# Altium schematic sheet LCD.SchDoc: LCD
size A4; Date: Not used; ApprovedBy: Not used; CheckedBy: Not used; Author: Not used; CompanyName: STMicroelectronics; DrawnBy: Not used; Engineer: Not used; Organization: Not used; Address1: Not used; Address2: Not used; Address3: Not used; Address4: Not used; DocumentNumber: Not used; Revision: Not used; SheetNumber: 13; SheetTotal: 23
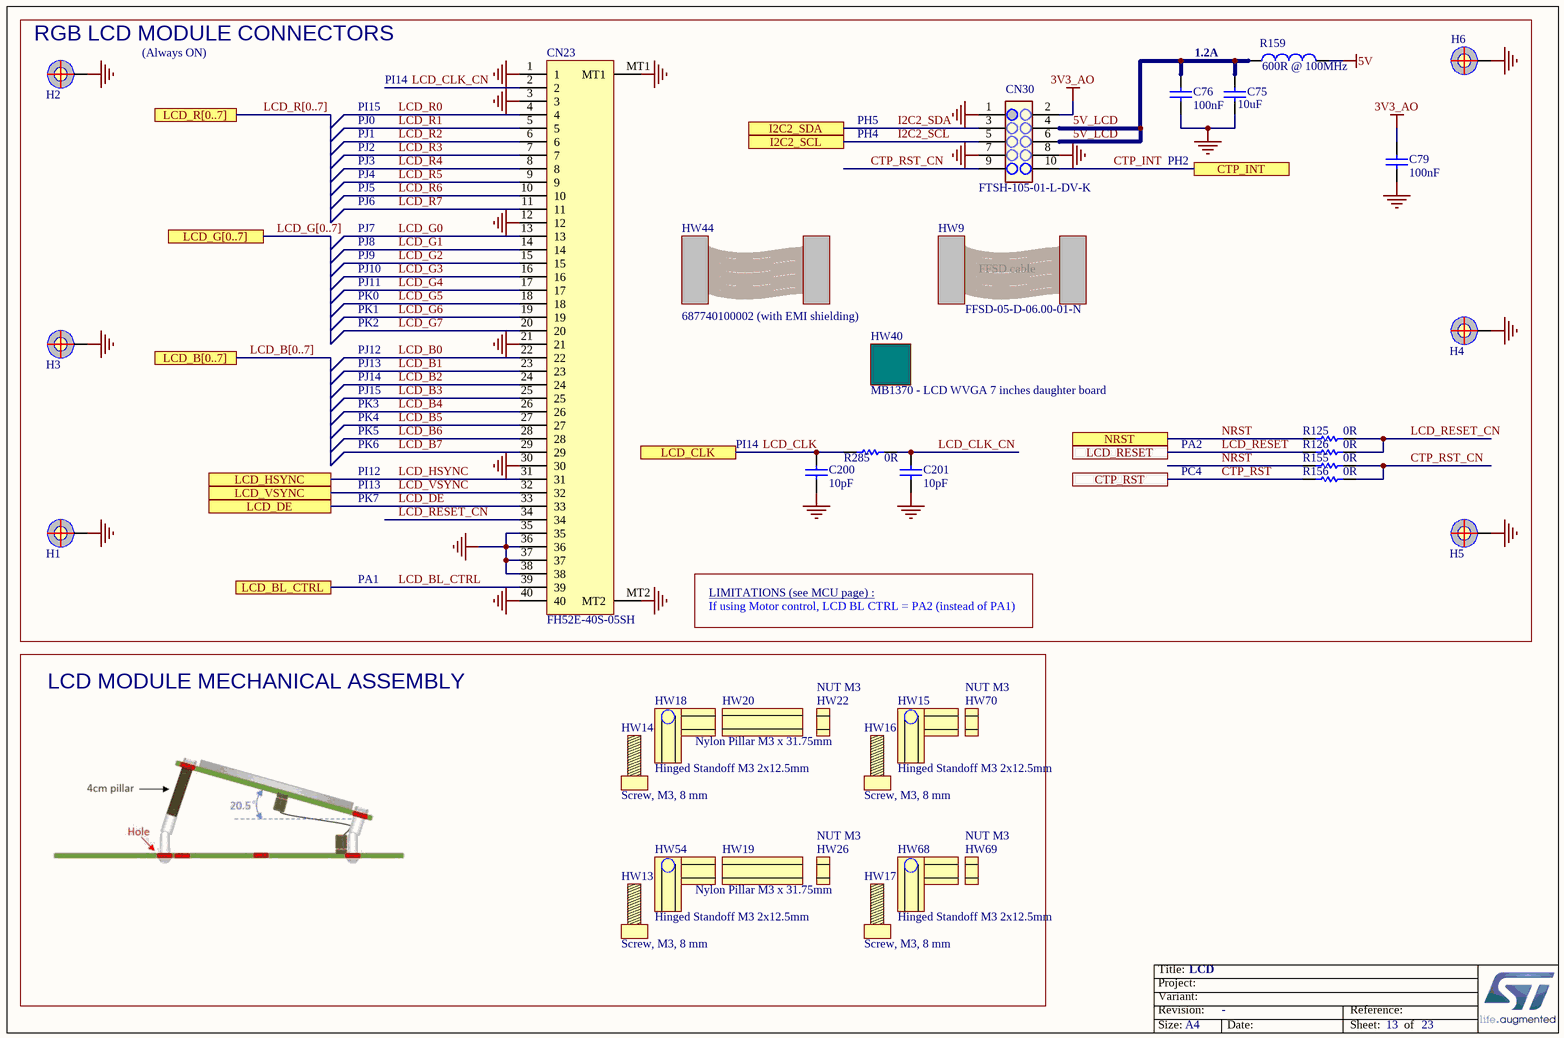
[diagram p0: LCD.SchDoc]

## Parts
C75  value 10uF  [C0805]  (hidden comment: Capacitor)
C76  value 100nF  [C0402]  (hidden comment: Capacitor)
C79  value 100nF  [C0402]  (hidden comment: Capacitor)
C200  value 10pF  [C0402]  (hidden comment: Capacitor)
C201  value 10pF  [C0402]  (hidden comment: Capacitor)
CN23  value FH52E-40S-05SH  [CON_HRS_FH52E-40S-05SH]  (hidden comment: FH52E-40S-0.5SH)
CN30  value FTSH-105-01-L-DV-K  [CON_SAMTEC_FTSH-105-01-L-DV-K]  (hidden comment: Header 5x2 Generic)
H1  POSITION HOLE  [PTH_M1261-3005-N_3P5X6_M3_H14]  (value not drawn)  (no BOM)
H2  POSITION HOLE  [PTH_M1261-3005-N_3P5X6_M3_H14]  (value not drawn)  (no BOM)
H3  POSITION HOLE  [PTH_M1261-3005-N_3P5X6_M3_H14]  (value not drawn)  (no BOM)
H4  POSITION HOLE  [PTH_M1261-3005-N_3P5X6_M3_H14]  (value not drawn)  (no BOM)
H5  POSITION HOLE  [PTH_M1261-3005-N_3P5X6_M3_H14]  (value not drawn)  (no BOM)
H6  POSITION HOLE  [PTH_M1261-3005-N_3P5X6_M3_H14]  (value not drawn)  (no BOM)
HW9  value FFSD-05-D-06.00-01-N  (hidden comment: FFSD05_CABLE)
HW13  value Screw, M3, 8 mm  (hidden comment: SCREW)  (mechanical)
HW14  value Screw, M3, 8 mm  (hidden comment: SCREW)  (mechanical)
HW15  value Hinged Standoff M3 2x12.5mm  (hidden comment: Hinged_Standoff)  (mechanical)
HW16  value Screw, M3, 8 mm  (hidden comment: SCREW)  (mechanical)
HW17  value Screw, M3, 8 mm  (hidden comment: SCREW)  (mechanical)
HW18  value Hinged Standoff M3 2x12.5mm  (hidden comment: Hinged_Standoff)  (mechanical)
HW19  value Nylon Pillar M3 x 31.75mm  (hidden comment: PILLAR)  (mechanical)
HW20  value Nylon Pillar M3 x 31.75mm  (hidden comment: PILLAR)  (mechanical)
HW22  value NUT M3  (hidden comment: NUT)  (mechanical)
HW26  value NUT M3  (hidden comment: NUT)  (mechanical)
HW40  value MB1370 - LCD WVGA 7 inches daughter board  [LCD_DRAWING_ROCKTEK_RK070ER9427L]  (hidden comment: Daughter_Board)
HW44  value 687740100002 (with EMI shielding)  (hidden comment: CABLE)  (mechanical)
HW54  value Hinged Standoff M3 2x12.5mm  (hidden comment: Hinged_Standoff)  (mechanical)
HW68  value Hinged Standoff M3 2x12.5mm  (hidden comment: Hinged_Standoff)  (mechanical)
HW69  value NUT M3  (hidden comment: NUT)  (mechanical)
HW70  value NUT M3  (hidden comment: NUT)  (mechanical)
R125  value 0R  [R0603]  (hidden comment: Resistor)
R126  value 0R  [R0603]  (hidden comment: Resistor)
R155  value 0R  [R0603]  (hidden comment: Resistor)
R156  value 0R  [R0603]  (hidden comment: Resistor)
R159  value 600R @ 100MHz  [IND_0603_H0P8]  (hidden comment: Inductor)
R285  value 0R  [R0603]  (hidden comment: Resistor)

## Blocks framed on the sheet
RGB LCD MODULE CONNECTORS: C75 C76 C79 C200 C201 CN23 CN30 H1-H6 HW9 HW40 HW44 R125 R126 R155 R156 R159 R285
LCD MODULE MECHANICAL ASSEMBLY: HW13-HW20 HW22 HW26 HW54 HW68-HW70

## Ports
CTP_INT, CTP_RST, I2C2_SCL, I2C2_SDA, LCD_B[0..7], LCD_BL_CTRL, LCD_CLK, LCD_DE, LCD_G[0..7], LCD_HSYNC, LCD_R[0..7], LCD_RESET, LCD_VSYNC, NRST

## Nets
3V3_AO: C79.2 CN30.2
5V: R159.2
GND: C75.1 C76.2 C79.1 C200.1 C201.1 CN23.1 CN23.3 CN23.12 CN23.21 CN23.30 CN23.35 CN23.36 CN23.37 CN23.38 CN23.40 CN23.MT1 CN23.MT2 CN30.1 CN30.7 CN30.8 H1.1 H2.1 H3.1 H4.1 H5.1 H6.1
5V_LCD: C75.2 C76.1 CN30.4 CN30.6 R159.1
CTP_INT: CN30.10 ; port CTP_INT
CTP_RST: R156.1 ; port CTP_RST
CTP_RST_CN: CN30.9 R155.2 R156.2
I2C2_SCL: CN30.5 ; port I2C2_SCL
I2C2_SDA: CN30.3 ; port I2C2_SDA
LCD_B0: CN23.22
LCD_B1: CN23.23
LCD_B2: CN23.24
LCD_B3: CN23.25
LCD_B4: CN23.26
LCD_B5: CN23.27
LCD_B6: CN23.28
LCD_B7: CN23.29
LCD_BL_CTRL: CN23.39 ; port LCD_BL_CTRL
LCD_CLK: C200.2 R285.1 ; port LCD_CLK
LCD_CLK_CN: C201.2 CN23.2 R285.2
LCD_DE: CN23.33 ; port LCD_DE
LCD_G0: CN23.13
LCD_G1: CN23.14
LCD_G2: CN23.15
LCD_G3: CN23.16
LCD_G4: CN23.17
LCD_G5: CN23.18
LCD_G6: CN23.19
LCD_G7: CN23.20
LCD_HSYNC: CN23.31 ; port LCD_HSYNC
LCD_R0: CN23.4
LCD_R1: CN23.5
LCD_R2: CN23.6
LCD_R3: CN23.7
LCD_R4: CN23.8
LCD_R5: CN23.9
LCD_R6: CN23.10
LCD_R7: CN23.11
LCD_RESET: R126.1 ; port LCD_RESET
LCD_RESET_CN: CN23.34 R125.2 R126.2
LCD_VSYNC: CN23.32 ; port LCD_VSYNC
NRST: R125.1 R155.1 ; port NRST

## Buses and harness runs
bus LCD_B[0..7] = port LCD_B[0..7]
bus LCD_G[0..7] = port LCD_G[0..7]
bus LCD_R[0..7] = port LCD_R[0..7]

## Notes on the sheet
- (Always ON)
- PI15
- PI14
- 1.2A
- PJ0
- PJ1
- PJ2
- PJ3
- PJ4
- PH5
- PH4
- PH2
- PJ5
- PJ6
- PJ7
- PJ8
- PJ9
- PJ10
- PJ11
- PK0
- PK1
- PK2
- PJ12
- PJ13
- PJ14
- PJ15
- PK3
- PK4
- PK5
- PK6
- PA2
- PI12
- PI13
- PK7
- PC4
- PA1
- LIMITATIONS (see MCU page) :
- If using Motor control, LCD BL CTRL = PA2 (instead of PA1)

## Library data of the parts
C75 = MCD-00014: Capacitor, MLCC, 10uF, 25V, X5R, 10%, 0805, T=0,85mm; Manufacturer_Part_Number: CC0805KRX5R8BB106; Manufacturer: YAGEO; Provided_By: SUBCO; ECCN_US: EAR99; ECCN_EU: NEC
C76 C79 = MCD-00006: Capacitor, MLCC, 100nF, 16V, X7R, 10%, 0402, T=0.5mm; Manufacturer_Part_Number: CC0402KRX7R7BB104; Manufacturer: YAGEO; Alternate_Manufacturer_Part_Number: GCM155R71C104KA55D; Alternate_Manufacturer: MURATA; Provided_By: SUBCO; ECCN_US: EAR99; ECCN_EU: NEC
C200 C201 = MCD-00015: Capacitor, MLCC, 10pF, 50V, NPO, 5%, 0402, T=0,5mm; Manufacturer_Part_Number: CC0402JRNPO9BN100; Manufacturer: YAGEO; ECCN_US: EAR99; ECCN_EU: NEC; Provided_By: SUBCO
CN23 = MCD-01992: FFC et FPC connector 0.5MM 40P LNG MTL FITNG SMT VERT MNT; Manufacturer: HIROSE; ECCN_US: EAR99; ECCN_EU: NEC; Provided_By: SUBCO
CN30 = MCD-00610: Surface mount, vertical male connector. Double row of 5 pins, 1.27mm pitch, 3.05mm lead. Mates with FFSD connector; Manufacturer: SAMTEC; Alternate_Manufacturer_Part_Number: P127B-2x05MGF-079-1A; Alternate_Manufacturer: JIUBABA; Provided_By: SUBCO
H1-H6 = MCD-00035: POSITION HOLE C6D3R5; Part_Type: Mechanical
HW9 = MCD-00612: FFSD series Ribbon cable pitch1.27mm 5pin x 2row, 15cm length.; Part_Type: Misc; Manufacturer: SAMTEC; ECCN_US: EAR99; ECCN_EU: NEC; Provided_By: SUBCO
HW13 HW14 HW16 HW17 = MCD-01711: Screw, M3, 8 mm, Stainless Steel; Part_Type: Mechanical; Manufacturer: ETTINGER; Provided_By: SUBCO
HW15 HW18 HW54 HW68 = MCD-01710: M3 2x12.5mm male to female Hinged Hex Standoff made of brass with nickel plated finish; Part_Type: Mechanical; Manufacturer: ETTINGER; Alternate_Manufacturer_Part_Number: 14.04.3.00034; Alternate_Manufacturer: JIUBABA; Provided_By: SUBCO
HW19 HW20 = MCD-01841: Nylon Pillar M3 x 31.75mm Male/Female; Part_Type: Mechanical; Manufacturer_Part_Number: 4820; Manufacturer: KEYSTONE ELECTRONICS; ECCN_US: EAR99; ECCN_EU: NEC; Provided_By: SUBCO
HW22 HW26 HW69 HW70 = MCD-01354: Nut, Steel, M3; Part_Type: Mechanical; Manufacturer_Part_Number: 4708; Manufacturer: Keystone Electronics
HW40 = MCD-01035: MB1370 - LCD WVGA 7 inches daughter board; Part_Type: Misc; Manufacturer: STMICROELECTRONICS; Provided_By: SUBCO with ST control
HW44 = MCD-02049: FFC/FPC Flex Cable, Opposite Side Contacts, WR-FFC 0.5mm Type 2 40P 100mm length, customized with EMI shielding; Part_Type: Mechanical; Manufacturer: WURTH ELEKTRONIK; Order_Code_RS: 1222740; ECCN_US: EAR99; ECCN_EU: NEC; Provided_By: SUBCO
R125 R126 R155 R156 R285 = MCD-00056: Resistor,0R,0603,5%,1/10W; Manufacturer_Part_Number: RC0603JR-070RL; Manufacturer: YAGEO; Provided_By: SUBCO; ECCN_US: EAR99; ECCN_EU: NEC
R159 = MCD-00593: Ferrite bead, 600R @ 100MHz,  1.3A, 150mOhm, 0603; Manufacturer_Part_Number: BLM18KG601SN1D; Manufacturer: MURATA; ECCN_US: EAR99; ECCN_EU: NEC; Provided_By: SUBCO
